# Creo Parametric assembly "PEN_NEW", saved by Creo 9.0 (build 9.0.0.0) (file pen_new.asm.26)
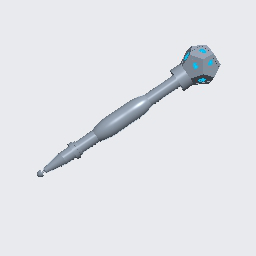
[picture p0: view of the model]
Units: millimeter Newton Second (mmNs); MM, TONNE, SECS

Created from: PEN.ASM

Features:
  1. component "01_STYLUS_HALF", "STYLUS_BOTTOM_V2.PRT"
  2. component "02_NIB_HOLDER", "NIB_HOLDER.PRT"
  3. component "03_NIB_BASE", "NIB_BASE.PRT"
  4. component "04_METAL_ROD", "METAL_ROD.PRT"
  5. component "01_STYLUS_HALF", "STYLUS_BOTTOM_V2.PRT"
  6. component "05_RING", "RING.PRT"
  7. component "06_DODECA_STYLUS_HALF", "DODECA_STYLUS_HALF.PRT"
  8. component "07_D_RING", "D_RING.PRT"
  9. component "08_DODECA_LID", "DODECA_LID.PRT"
  10. component "09_TIP", "TIP.PRT"

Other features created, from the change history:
  component "DODECA_V3.PRT"
  component "XIAO-NRF52840_V15.ASM"
  component "STYLUS-TOP.PRT"
  component "DODECA_V3_BOTTOM.PRT"
  component "DODECA.ASM"
  component "NIB_BASE.PRT"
